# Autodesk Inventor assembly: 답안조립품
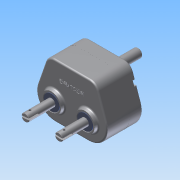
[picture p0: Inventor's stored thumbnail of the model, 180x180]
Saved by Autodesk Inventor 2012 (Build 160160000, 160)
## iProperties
Created: 2014-12
Part Number: 답안조립품
Document SubType Name: Assembly
Designer: Owner
Author: Owner
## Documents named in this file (13)
- C:\Documents and Settings\Owner\바탕 화면\441208V1022\답안조립품.iam
- C:\Documents and Settings\Owner\바탕 화면\441208V1022\1-본체.ipt
- C:\Documents and Settings\Owner\바탕 화면\441208V1022\서브축.ipt
- C:\Documents and Settings\Owner\바탕 화면\441208V1022\베어링- 6202.ipt
- C:\Documents and Settings\Owner\바탕 화면\441208V1022\메인축.ipt
- C:\Documents and Settings\Owner\바탕 화면\441208V1022\베어링- 6203.ipt
- C:\Documents and Settings\Owner\바탕 화면\441208V1022\오일시일-D-15.ipt
- C:\Documents and Settings\Owner\바탕 화면\441208V1022\메인기어.ipt
- C:\Documents and Settings\Owner\바탕 화면\441208V1022\키5x5.ipt
- C:\Documents and Settings\Owner\바탕 화면\441208V1022\멈춤링.ipt
- C:\Documents and Settings\Owner\바탕 화면\441208V1022\서브기어.ipt
- C:\Documents and Settings\Owner\바탕 화면\441208V1022\커버.ipt
- C:\Documents and Settings\Owner\바탕 화면\441208V1022\오일시일-D-17.ipt
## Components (13 placed, 6 different names)
1. 1-본체:1
2. KS B 2023 6202 - 15 x 35 x 11:1
3. KS B 2023 6202 - 15 x 35 x 11:2
4. KS B 2023 6203 - 17 x 40 x 12:1
5. KS B 2804 D D - 15 30 7:1
6. KS B 2804 D D - 15 30 7:2
7. KS B 1336 17 x 1:1
8. KS B 1336 17 x 1:2
9. KS B 1336 17 x 1:3
10. KS B 2023 6203 - 17 x 40 x 12:2
11. KS B 2023 6203 - 17 x 40 x 12:3
12. KS B 2023 6203 - 17 x 40 x 12:4
13. KS B 2804 D D - 17 30 8:1
